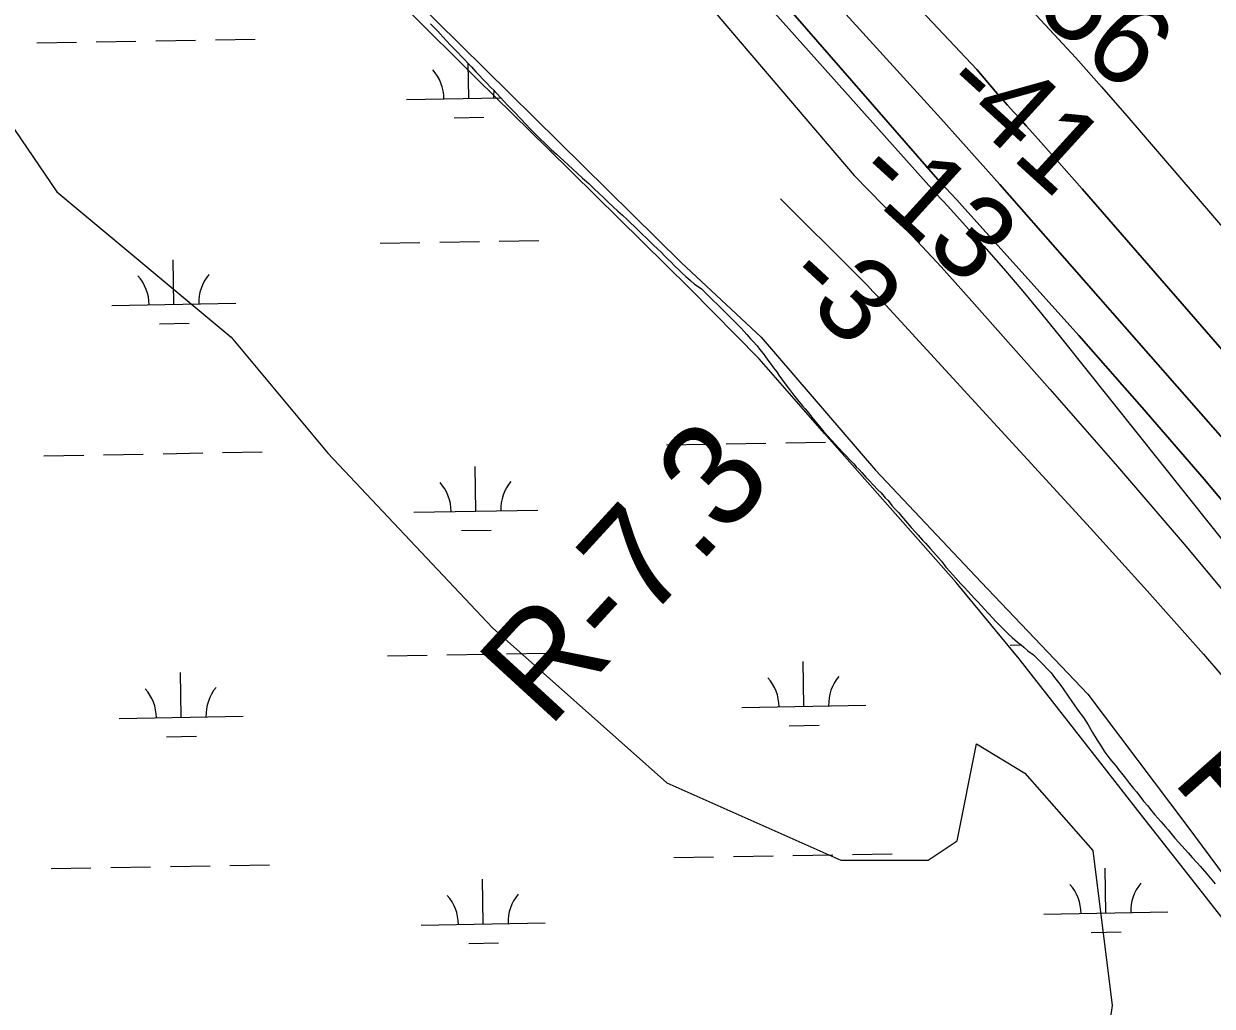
# Model space of a CAD drawing. Extents: x 3903937 to 3942190, y 260677 to 286651.
# Drawn here: x 3924784 to 3925742, y 274777 to 275569 of the extents above; entities that cross this region are included whole.
import ezdxf

# ---------------------------------------------------------------- set-up
doc = ezdxf.new("R2010")
doc.units = 0
for name, color, linetype in [('V-RIVR-EDGE', 7, 'Continuous'), ('V-RIVR-RANG', 7, 'Continuous'), ('V-RIVR-RANG-IDEN', 7, 'Continuous'), ('V-RRAP-FSHR', 7, 'Continuous'), ('V-SITE-VEGE', 7, 'Continuous'), ('V-TOPO-DPTH', 7, 'Continuous'), ('V-TOPO-MAJR', 7, 'Continuous'), ('V-TOPO-MINR', 7, 'Continuous'), ('V-UTIL-IDEN', 7, 'Continuous'), ('V-WETL-SWMP', 7, 'Continuous')]:
    doc.layers.add(name, color=color, linetype=linetype)

msp = doc.modelspace()

# ---------------------------------------------------------------- linework, layer by layer
at = {"layer": 'V-RIVR-EDGE'}
msp.add_lwpolyline([(3925056.93, 275630.21), (3925314.06, 275376.23), (3925378.09, 275316.4), (3925470.44, 275209.35), (3925555.46, 275119.09), (3925641.52, 275028.83), (3925721.28, 274922.83), (3925794.75, 274824.18), (3925865.07, 274722.37), (3925978.42, 274588.03), (3926090.72, 274452.64), (3926156.84, 274391.77), (3926205.11, 274351.89), (3926231.35, 274303.61), (3926349.95, 274187.11), (3926419.22, 274112.6), (3926441.26, 274069.56), (3926492.69, 274003.44), (3926517.87, 273967.76), (3926556.71, 273913.19), (3926592.39, 273867.01), (3926597.89, 273845.33)], dxfattribs=at)
at = {"layer": 'V-RRAP-FSHR'}
msp.add_lwpolyline([(3925882.32, 274679.45), (3925832.95, 274742.4), (3925783.58, 274805.36), (3925734.21, 274868.31), (3925684.85, 274931.26), (3925635.48, 274994.21), (3925586.11, 275057.16), (3925535.46, 275118.7), (3925482.19, 275178.75), (3925429.34, 275238.8), (3925376.48, 275298.86), (3925320.35, 275355.82), (3925263.39, 275411.99), (3925206.43, 275468.16), (3925149.46, 275524.33), (3925092.69, 275580.69)], dxfattribs=at)
at = {"layer": 'V-SITE-VEGE'}
for p, q in [((3924693.45, 275605.34), (3924810.49, 275433.59)), ((3924810.49, 275433.59), (3924950.95, 275316.49)), ((3924950.95, 275316.49), (3925028.98, 275222.81)), ((3925028.98, 275222.81), (3925161.63, 275082.29)), ((3925161.63, 275082.29), (3925302.08, 274957.37)), ((3925536.17, 274910.53), (3925551.77, 274988.6)), ((3925551.77, 274988.6), (3925590.79, 274965.18)), ((3925590.79, 274965.18), (3925645.41, 274902.73)), ((3925302.08, 274957.37), (3925442.53, 274894.92)), ((3925512.76, 274894.92), (3925536.17, 274910.53)), ((3925645.41, 274902.73), (3925661.02, 274777.82)), ((3925442.53, 274894.92), (3925512.76, 274894.92)), ((3925661.02, 274777.82), (3925645.41, 274668.52))]:
    msp.add_line(p, q, dxfattribs=at)
at = {"layer": 'V-TOPO-DPTH'}
for points in [[(3924821.61, 276306.42), (3925552, 275532.15), (3925555, 275528.64), (3925557.97, 275525.11), (3925560.91, 275521.55), (3925563.86, 275518), (3925566.85, 275514.49), (3925569.89, 275511.01), (3925572.96, 275507.57), (3925576.8, 275503.34), (3925581.82, 275497.79), (3925586.83, 275492.25), (3925591.83, 275486.7), (3925596.83, 275481.14), (3925603.65, 275473.54), (3925612.04, 275464.16), (3925620.39, 275454.76), (3925628.7, 275445.31), (3925636.98, 275435.84), (3926014.76, 275001.62)], [(3926014.76, 275001.62), (3925636.98, 275435.84), (3925628.7, 275445.31), (3925620.39, 275454.76), (3925612.04, 275464.16), (3925603.65, 275473.54), (3925596.83, 275481.14), (3925591.83, 275486.7), (3925586.83, 275492.25), (3925581.82, 275497.79), (3925576.8, 275503.34), (3925572.96, 275507.57), (3925569.89, 275511.01), (3925566.85, 275514.49), (3925563.86, 275518), (3925560.91, 275521.55), (3925557.97, 275525.11), (3925555, 275528.64), (3925552, 275532.15), (3924821.61, 276306.42)], [(3924736.95, 276286.28), (3925453.18, 275446.62), (3925476.86, 275422.37), (3925500.25, 275397.86), (3925523.23, 275372.96), (3925545.93, 275347.8), (3925610.82, 275274.62), (3925665.32, 275212.3), (3925719.23, 275149.48), (3925772.27, 275085.93)], [(3925784.62, 275143.1), (3925735.36, 275202.01), (3925685.12, 275260.1), (3925634.24, 275317.63), (3925540.2, 275422.19), (3925535.83, 275427.01), (3925531.44, 275431.8), (3925527.01, 275436.57), (3925522.55, 275441.3), (3924958.23, 276088.66)], [(3924958.23, 276088.66), (3925522.55, 275441.3), (3925527.01, 275436.57), (3925531.44, 275431.8), (3925535.83, 275427.01), (3925540.2, 275422.19), (3925634.24, 275317.63), (3925685.12, 275260.1), (3925735.36, 275202.01), (3925784.62, 275143.1)], [(3926824.12, 273970.48), (3926811.3, 273986.1), (3926798.41, 274001.67), (3926785.48, 274017.2), (3926685.26, 274137.08), (3926622.11, 274212.46), (3926558.86, 274287.76), (3926495.45, 274362.92), (3926431.94, 274438), (3926049.4, 274889.23), (3926031.36, 274910.53), (3926013.33, 274931.84), (3925995.33, 274953.16), (3925977.33, 274974.5), (3925959.28, 274995.79), (3925941.15, 275017.01), (3925922.88, 275038.11), (3925904.53, 275059.14), (3925586.2, 275421.6), (3925570.47, 275439.42), (3925554.69, 275457.2), (3925538.82, 275474.89), (3925522.89, 275492.54), (3925400.05, 275627.99)], [(3926824.12, 273970.48), (3926811.3, 273986.1), (3926798.41, 274001.67), (3926785.48, 274017.2), (3926685.26, 274137.08), (3926622.11, 274212.46), (3926558.86, 274287.76), (3926495.45, 274362.92), (3926431.94, 274438), (3926049.4, 274889.23), (3926031.36, 274910.53), (3926013.33, 274931.84), (3925995.33, 274953.16), (3925977.33, 274974.5), (3925959.28, 274995.79), (3925941.15, 275017.01), (3925922.88, 275038.11), (3925904.53, 275059.14), (3925586.2, 275421.6), (3925570.47, 275439.42), (3925554.69, 275457.2), (3925538.82, 275474.89), (3925522.89, 275492.54), (3925400.05, 275627.99)]]:
    msp.add_lwpolyline(points, dxfattribs=at)
at = {"layer": 'V-TOPO-MAJR'}
msp.add_lwpolyline([(3925589.3, 275587.01), (3925610.66, 275564.32), (3925631.77, 275541.41), (3925652.52, 275518.17), (3925673.03, 275494.71), (3925880.17, 275253.91), (3925917.39, 275211.56), (3925955.19, 275169.75), (3925993.86, 275128.75), (3926033.12, 275088.29), (3926065.15, 275055.97), (3926088.86, 275032.11), (3926112.61, 275008.28), (3926136.42, 274984.52), (3926160.27, 274960.8), (3926235.04, 274886.62), (3926933.51, 274261.18)], dxfattribs=at)
at = {"layer": 'V-TOPO-MINR'}
for points in [[(3924821.61, 276306.42), (3925552, 275532.15), (3925555, 275528.64), (3925557.97, 275525.11), (3925560.91, 275521.55), (3925563.86, 275518), (3925566.85, 275514.49), (3925569.89, 275511.01), (3925572.96, 275507.57), (3925576.8, 275503.34), (3925581.82, 275497.79), (3925586.83, 275492.25), (3925591.83, 275486.7), (3925596.83, 275481.14), (3925603.65, 275473.54), (3925612.04, 275464.16), (3925620.39, 275454.76), (3925628.7, 275445.31), (3925636.98, 275435.84), (3926014.76, 275001.62)], [(3924736.95, 276286.28), (3925453.18, 275446.62), (3925476.86, 275422.37), (3925500.25, 275397.86), (3925523.23, 275372.96), (3925545.93, 275347.8), (3925610.82, 275274.62), (3925665.32, 275212.3), (3925719.23, 275149.48), (3925772.27, 275085.93)], [(3924865.01, 276164.04), (3925522.61, 275428.37), (3925525.51, 275425.33), (3925528.35, 275422.24), (3925557.6, 275389.63), (3925573.47, 275371.62), (3925589.12, 275353.44), (3925604.46, 275334.99), (3925619.58, 275316.36), (3925921.58, 274937.63)], [(3924958.23, 276088.66), (3925522.55, 275441.3), (3925527.01, 275436.57), (3925531.44, 275431.8), (3925535.83, 275427.01), (3925540.2, 275422.19), (3925634.24, 275317.63), (3925685.12, 275260.1), (3925735.36, 275202.01), (3925784.62, 275143.1)], [(3925400.05, 275627.99), (3925522.89, 275492.54), (3925538.82, 275474.89), (3925554.69, 275457.2), (3925570.47, 275439.42), (3925586.2, 275421.6), (3925904.53, 275059.14), (3925922.88, 275038.11), (3925941.15, 275017.01), (3925959.28, 274995.79), (3925977.33, 274974.5), (3925995.33, 274953.16), (3926013.33, 274931.84), (3926031.36, 274910.53), (3926049.4, 274889.23), (3926431.94, 274438), (3926495.45, 274362.92), (3926558.86, 274287.76), (3926622.11, 274212.46), (3926685.26, 274137.08), (3926785.48, 274017.2), (3926798.41, 274001.67), (3926811.3, 273986.1), (3926824.12, 273970.48)], [(3925393.86, 275427.91), (3925454.73, 275367.26), (3925459.3, 275362.65), (3925463.82, 275358), (3925468.29, 275353.29), (3925472.71, 275348.55), (3925643.67, 275162.56), (3925689.4, 275112.02), (3925734.59, 275061.01), (3925778.97, 275009.3), (3925822.8, 274957.11), (3925860.77, 274911.17), (3925885.01, 274881.44), (3925908.98, 274851.49), (3925932.53, 274821.21), (3925955.8, 274790.71), (3926119.11, 274573.66), (3926224.06, 274434.65), (3926329.31, 274295.86), (3926435.01, 274157.42), (3926541, 274019.2), (3927113.99, 273274.53)]]:
    msp.add_lwpolyline(points, dxfattribs=at)
at = {"layer": 'V-WETL-SWMP'}
for p, q in [((3925111.7, 275568.89), (3925113.84, 275566.75)), ((3925113.84, 275566.75), (3925117.26, 275563.21)), ((3925117.26, 275563.21), (3925119.5, 275560.74)), ((3924794.34, 275553.46), (3924826.34, 275554.02)), ((3924842.33, 275554.3), (3924874.33, 275554.87)), ((3924890.33, 275555.15), (3924922.32, 275555.71)), ((3924938.32, 275555.99), (3924970.31, 275556.56)), ((3925119.5, 275560.74), (3925124.31, 275555.49)), ((3925124.31, 275555.49), (3925127.95, 275551.74)), ((3925127.95, 275551.74), (3925130.19, 275549.27)), ((3925130.19, 275549.27), (3925133.62, 275545.84)), ((3925133.62, 275545.84), (3925136.71, 275542.62)), ((3925136.71, 275542.62), (3925138.96, 275540.37)), ((3925138.96, 275540.37), (3925142.27, 275536.73)), ((3925142.5, 275508.84), (3925142, 275537.03)), ((3925142.27, 275536.73), (3925144.63, 275534.15)), ((3925144.63, 275534.15), (3925148.37, 275530.29)), ((3925148.37, 275530.29), (3925150.72, 275527.72)), ((3925150.72, 275527.72), (3925154.46, 275523.86)), ((3925154.46, 275523.86), (3925156.92, 275521.39)), ((3925156.92, 275521.39), (3925160.45, 275517.64)), ((3925160.45, 275517.64), (3925162.8, 275515.28)), ((3925162.8, 275515.28), (3925165.05, 275512.82)), ((3925092.5, 275507.96), (3925168.45, 275509.29)), ((3925165.05, 275512.82), (3925168.47, 275509.28)), ((3925168.47, 275509.28), (3925170.61, 275506.71)), ((3925170.61, 275506.71), (3925174.03, 275503.17)), ((3925174.03, 275503.17), (3925176.17, 275500.92)), ((3925176.17, 275500.92), (3925179.16, 275497.81)), ((3925179.16, 275497.81), (3925183.97, 275492.77)), ((3925130.77, 275493.2), (3925154.77, 275493.62)), ((3925183.97, 275492.77), (3925188.78, 275487.84)), ((3925188.78, 275487.84), (3925191.77, 275484.62)), ((3925191.77, 275484.62), (3925194.02, 275482.47)), ((3925194.02, 275482.47), (3925197.44, 275478.94)), ((3925197.44, 275478.94), (3925199.9, 275476.47)), ((3925199.9, 275476.47), (3925203.86, 275472.61)), ((3925203.86, 275472.61), (3925206.53, 275470.04)), ((3925206.53, 275470.04), (3925209.1, 275467.57)), ((3925209.1, 275467.57), (3925213.16, 275463.82)), ((3925213.16, 275463.82), (3925215.83, 275461.35)), ((3925215.83, 275461.35), (3925219.68, 275457.81)), ((3925219.68, 275457.81), (3925222.04, 275455.77)), ((3925222.04, 275455.77), (3925227.06, 275451.27)), ((3925227.06, 275451.27), (3925229.74, 275448.8)), ((3925229.74, 275448.8), (3925234.23, 275444.62)), ((3925234.23, 275444.62), (3925239.25, 275440.12)), ((3925239.25, 275440.12), (3925243.1, 275436.36)), ((3925243.1, 275436.36), (3925248.02, 275431.75)), ((3925248.02, 275431.75), (3925250.8, 275429.07)), ((3925250.8, 275429.07), (3925255.19, 275425)), ((3925255.19, 275425), (3925259.04, 275421.46)), ((3925259.04, 275421.46), (3925262.78, 275417.92)), ((3925262.78, 275417.92), (3925266.52, 275414.59)), ((3925266.52, 275414.59), (3925270.58, 275410.84)), ((3925270.58, 275410.84), (3925272.94, 275408.59)), ((3925272.94, 275408.59), (3925276.25, 275405.48)), ((3925276.25, 275405.48), (3925280.1, 275401.62)), ((3925280.1, 275401.62), (3925282.35, 275399.47)), ((3925282.35, 275399.47), (3925285.77, 275396.04)), ((3925071.13, 275392.13), (3925103.13, 275392.69)), ((3925119.12, 275392.98), (3925151.12, 275393.54)), ((3925167.12, 275393.82), (3925199.11, 275394.38)), ((3925285.77, 275396.04), (3925288.87, 275393.15)), ((3925288.87, 275393.15), (3925291.43, 275390.57)), ((3925291.43, 275390.57), (3925294.54, 275387.68)), ((3925294.54, 275387.68), (3925297.64, 275384.78)), ((3925297.64, 275384.78), (3925300.31, 275381.99)), ((3925300.31, 275381.99), (3925303.09, 275379.31)), ((3924904.91, 275342.77), (3924904.28, 275378.76)), ((3925303.09, 275379.31), (3925305.66, 275376.74)), ((3925305.66, 275376.74), (3925308.44, 275373.95)), ((3925308.44, 275373.95), (3925312.07, 275370.41)), ((3925312.07, 275370.41), (3925314.42, 275367.95)), ((3925314.42, 275367.95), (3925317.63, 275365.16)), ((3925317.63, 275365.16), (3925321.16, 275362.16)), ((3925321.16, 275362.16), (3925324.48, 275359.15)), ((3925324.48, 275359.15), (3925327.36, 275357.11)), ((3925327.36, 275357.11), (3925330.05, 275355.35)), ((3925330.05, 275355.35), (3925333.78, 275351.56)), ((3925333.78, 275351.56), (3925338.81, 275346.8)), ((3924854.92, 275341.89), (3924954.9, 275343.65)), ((3925338.81, 275346.8), (3925343.94, 275341.97)), ((3925343.94, 275341.97), (3925346.61, 275339.29)), ((3925346.61, 275339.29), (3925350.89, 275335)), ((3925350.89, 275335), (3925354.42, 275331.46)), ((3924893.18, 275327.13), (3924917.18, 275327.55)), ((3925354.42, 275331.46), (3925359.23, 275326.64)), ((3925359.23, 275326.64), (3925362.01, 275323.64)), ((3925362.01, 275323.64), (3925366.6, 275318.49)), ((3925366.6, 275318.49), (3925369.7, 275315.06)), ((3925369.7, 275315.06), (3925371.84, 275312.81)), ((3925371.84, 275312.81), (3925374.94, 275309.27)), ((3925374.94, 275309.27), (3925376.87, 275306.8)), ((3925376.87, 275306.8), (3925379.86, 275303.16)), ((3925379.86, 275303.16), (3925381.68, 275300.48)), ((3925381.68, 275300.48), (3925384.46, 275296.73)), ((3925384.46, 275296.73), (3925386.27, 275294.26)), ((3925386.27, 275294.26), (3925388.09, 275291.8)), ((3925388.09, 275291.8), (3925390.76, 275288.37)), ((3925390.76, 275288.37), (3925392.47, 275285.9)), ((3925392.47, 275285.9), (3925396.64, 275279.9)), ((3925396.64, 275279.9), (3925401.02, 275274.33)), ((3925401.02, 275274.33), (3925403.58, 275270.9)), ((3925403.58, 275270.9), (3925406.47, 275267.25)), ((3925406.47, 275267.25), (3925408.5, 275264.68)), ((3925408.5, 275264.68), (3925411.6, 275261.04)), ((3925411.6, 275261.04), (3925413.63, 275258.57)), ((3925413.63, 275258.57), (3925416.52, 275255.25)), ((3925416.52, 275255.25), (3925419.83, 275250.96)), ((3925419.83, 275250.96), (3925424.21, 275245.71)), ((3925424.21, 275245.71), (3925428.81, 275240.13)), ((3925428.81, 275240.13), (3925432.12, 275236.27)), ((3925302.03, 275229.67), (3925334.02, 275230.23)), ((3925350.02, 275230.51), (3925382.01, 275231.08)), ((3925398.01, 275231.36), (3925430.01, 275231.92)), ((3925432.12, 275236.27), (3925434.58, 275233.59)), ((3925434.58, 275233.59), (3925438.32, 275229.73)), ((3925438.32, 275229.73), (3925440.89, 275227.05)), ((3925440.89, 275227.05), (3925444.31, 275223.19)), ((3924800.2, 275220.83), (3924832.19, 275221.4)), ((3924848.19, 275221.68), (3924880.18, 275222.24)), ((3924896.18, 275222.52), (3924928.18, 275223.09)), ((3924944.17, 275223.37), (3924976.17, 275223.93)), ((3925444.31, 275223.19), (3925446.56, 275220.94)), ((3925446.56, 275220.94), (3925449.66, 275217.62)), ((3925449.66, 275217.62), (3925452.86, 275214.29)), ((3925148.35, 275176.21), (3925147.72, 275212.21)), ((3925452.86, 275214.29), (3925454.9, 275212.04)), ((3925454.9, 275212.04), (3925457.14, 275209.79)), ((3925457.14, 275209.79), (3925459.28, 275207.32)), ((3925459.28, 275207.32), (3925462.7, 275203.68)), ((3925462.7, 275203.68), (3925465.05, 275201.1)), ((3925465.05, 275201.1), (3925468.58, 275197.35)), ((3925468.58, 275197.35), (3925472.32, 275193.49)), ((3925472.32, 275193.49), (3925474.89, 275190.92)), ((3925474.89, 275190.92), (3925478.1, 275187.06)), ((3925478.1, 275187.06), (3925480.45, 275184.7)), ((3925480.45, 275184.7), (3925483.55, 275180.84)), ((3925483.55, 275180.84), (3925485.79, 275178.38)), ((3925098.36, 275175.33), (3925198.34, 275177.09)), ((3925485.79, 275178.38), (3925489.11, 275174.73)), ((3925489.11, 275174.73), (3925491.24, 275172.16)), ((3925491.24, 275172.16), (3925494.67, 275168.41)), ((3925136.62, 275160.57), (3925160.62, 275161)), ((3925494.67, 275168.41), (3925499.05, 275163.15)), ((3925499.05, 275163.15), (3925502.47, 275159.29)), ((3925502.47, 275159.29), (3925504.71, 275156.72)), ((3925504.71, 275156.72), (3925508.35, 275152.86)), ((3925508.35, 275152.86), (3925510.7, 275150.29)), ((3925510.7, 275150.29), (3925514.33, 275146.21)), ((3925514.33, 275146.21), (3925519.47, 275140.42)), ((3925519.47, 275140.42), (3925523.53, 275135.81)), ((3925523.53, 275135.81), (3925527.16, 275131.1)), ((3925527.16, 275131.1), (3925530.26, 275127.45)), ((3925530.26, 275127.45), (3925532.61, 275124.88)), ((3925532.61, 275124.88), (3925535.07, 275122.09)), ((3925535.07, 275122.09), (3925539.14, 275117.7)), ((3925539.14, 275117.7), (3925541.59, 275115.12)), ((3925541.59, 275115.12), (3925545.02, 275111.37)), ((3925545.02, 275111.37), (3925547.15, 275109.12)), ((3925547.15, 275109.12), (3925550.36, 275105.69)), ((3925550.36, 275105.69), (3925552.61, 275103.33)), ((3925552.61, 275103.33), (3925555.81, 275099.79)), ((3925555.81, 275099.79), (3925557.95, 275097.43)), ((3925557.95, 275097.43), (3925561.37, 275093.79)), ((3925561.37, 275093.79), (3925564.9, 275089.93)), ((3925564.9, 275089.93), (3925567.15, 275087.57)), ((3925567.15, 275087.57), (3925571.85, 275082.64)), ((3925571.85, 275082.64), (3925577.3, 275077.28)), ((3925577.3, 275077.28), (3925580.4, 275074.38)), ((3925580.4, 275074.38), (3925584.68, 275070.73)), ((3925578.82, 275068.34), (3925587.82, 275068.5)), ((3925584.68, 275070.73), (3925587.73, 275068.59)), ((3925587.73, 275068.59), (3925589.98, 275066.49)), ((3925589.98, 275066.49), (3925593.18, 275063.76)), ((3925076.99, 275059.51), (3925108.98, 275060.07)), ((3925124.98, 275060.35), (3925156.97, 275060.91)), ((3925172.97, 275061.2), (3925204.97, 275061.76)), ((3925412.6, 275018.98), (3925411.96, 275054.97)), ((3925593.18, 275063.76), (3925597.62, 275060.43)), ((3925597.62, 275060.43), (3925601.04, 275057.11)), ((3925601.04, 275057.11), (3925605.75, 275052.29)), ((3924910.76, 275010.14), (3924910.13, 275046.14)), ((3925605.75, 275052.29), (3925608.53, 275049.5)), ((3925608.53, 275049.5), (3925611.84, 275045.85)), ((3925611.84, 275045.85), (3925613.87, 275043.28)), ((3925613.87, 275043.28), (3925616.87, 275039.42)), ((3925616.87, 275039.42), (3925619.75, 275035.67)), ((3925619.75, 275035.67), (3925621.57, 275032.99)), ((3925621.57, 275032.99), (3925625.52, 275027.1)), ((3925625.52, 275027.1), (3925628.51, 275022.81)), ((3925362.6, 275018.1), (3925462.59, 275019.86)), ((3925628.51, 275022.81), (3925630.54, 275020.13)), ((3925630.54, 275020.13), (3925633.54, 275015.95)), ((3924860.77, 275009.26), (3924960.76, 275011.02)), ((3925633.54, 275015.95), (3925637.92, 275009.95)), ((3925637.92, 275009.95), (3925641.66, 275004.16)), ((3925400.87, 275003.34), (3925424.86, 275003.76)), ((3925641.66, 275004.16), (3925645.29, 274997.84)), ((3925645.29, 274997.84), (3925649.03, 274991.62)), ((3924899.04, 274994.5), (3924923.03, 274994.93)), ((3925649.03, 274991.62), (3925651.59, 274987.65)), ((3925651.59, 274987.65), (3925653.41, 274984.97)), ((3925653.41, 274984.97), (3925655.33, 274982.08)), ((3925655.33, 274982.08), (3925658.43, 274977.79)), ((3925658.43, 274977.79), (3925660.67, 274974.9)), ((3925660.67, 274974.9), (3925664.2, 274970.61)), ((3925664.2, 274970.61), (3925666.34, 274968.04)), ((3925666.34, 274968.04), (3925669.76, 274963.86)), ((3925669.76, 274963.86), (3925671.79, 274961.07)), ((3925671.79, 274961.07), (3925675.1, 274956.78)), ((3925675.1, 274956.78), (3925678.31, 274952.71)), ((3925678.31, 274952.71), (3925680.66, 274949.92)), ((3925680.66, 274949.92), (3925684.19, 274945.53)), ((3925684.19, 274945.53), (3925686.43, 274942.63)), ((3925686.43, 274942.63), (3925689.85, 274938.67)), ((3925689.85, 274938.67), (3925692.1, 274935.88)), ((3925692.1, 274935.88), (3925695.52, 274931.59)), ((3925695.52, 274931.59), (3925697.98, 274928.91)), ((3925697.98, 274928.91), (3925700.33, 274926.23)), ((3925700.33, 274926.23), (3925703.96, 274921.94)), ((3925703.96, 274921.94), (3925706.32, 274919.37)), ((3925706.32, 274919.37), (3925709.52, 274915.3)), ((3925709.52, 274915.3), (3925711.66, 274912.72)), ((3925711.66, 274912.72), (3925714.87, 274909.29)), ((3925714.87, 274909.29), (3925717, 274906.93)), ((3925717, 274906.93), (3925720.21, 274903.4)), ((3925720.21, 274903.4), (3925722.35, 274900.93)), ((3925307.88, 274897.04), (3925339.88, 274897.61)), ((3925355.87, 274897.89), (3925387.87, 274898.45)), ((3925403.87, 274898.73), (3925435.86, 274899.3)), ((3925451.86, 274899.58), (3925483.85, 274900.14)), ((3925722.35, 274900.93), (3925725.66, 274897.07)), ((3925725.66, 274897.07), (3925729.41, 274893)), ((3925729.41, 274893), (3925732.08, 274890.1)), ((3924806.05, 274888.21), (3924838.05, 274888.77)), ((3924854.04, 274889.06), (3924886.04, 274889.62)), ((3924902.04, 274889.9), (3924934.03, 274890.46)), ((3924950.03, 274890.75), (3924982.02, 274891.31)), ((3925656.04, 274852.42), (3925655.4, 274888.42)), ((3925732.08, 274890.1), (3925737.32, 274883.88)), ((3925737.32, 274883.88), (3925741.38, 274879.28)), ((3925154.21, 274843.59), (3925153.57, 274879.58)), ((3925741.38, 274879.28), (3925744.16, 274875.85)), ((3925104.21, 274842.71), (3925204.2, 274844.47)), ((3925606.04, 274851.54), (3925706.03, 274853.3)), ((3925644.31, 274836.78), (3925668.31, 274837.21)), ((3925142.48, 274827.95), (3925166.48, 274828.37))]:
    msp.add_line(p, q, dxfattribs=at)
for centre, start, end in [((3925087.25, 275508.34), 0.23658, 41.78024), ((3925197.72, 275510.28), 171.89138, 181.78024), ((3924849.67, 275342.27), 0.23658, 41.78024), ((3924960.14, 275344.21), 140.23658, 181.78024), ((3925093.11, 275175.72), 0.23658, 41.78024), ((3925203.58, 275177.66), 140.23658, 181.78024), ((3925357.35, 275018.48), 0.23658, 41.78024), ((3925467.82, 275020.42), 140.23658, 181.78024), ((3924855.52, 275009.65), 0.23658, 41.78024), ((3924965.99, 275011.59), 140.23658, 181.78024), ((3925600.79, 274851.93), 0.23658, 41.78024), ((3925711.26, 274853.87), 140.23658, 181.78024), ((3925098.96, 274843.09), 0.23658, 41.78024), ((3925209.43, 274845.04), 140.23658, 181.78024)]:
    msp.add_arc(centre, 35.25, start, end, dxfattribs=at)

# ---------------------------------------------------------------- texts
at = {"layer": 'V-RIVR-RANG'}
for s, rotation, p in [('-56', 317.64589, (3925575.8, 275599.18)), ('-41', 317.64589, (3925520.13, 275514.6)), ('-13', 317.64589, (3925450.05, 275443.18)), ('-3', 317.35833, (3925393.85, 275359.45))]:
    msp.add_text(s, height=67, rotation=rotation, dxfattribs=at).set_placement(p)
at = {"layer": 'V-RIVR-RANG-IDEN'}
msp.add_text('R-7.3', height=83, rotation=47.50421, dxfattribs=at).set_placement((3925206.76, 275000.33))
at = {"layer": 'V-UTIL-IDEN'}
msp.add_text('TEXAS EASTERN TRANSMISSION CO.', height=82.9998, rotation=41.45428, dxfattribs=at).set_placement((3925767.18, 274888.8))

doc.saveas('drawing.dxf')
